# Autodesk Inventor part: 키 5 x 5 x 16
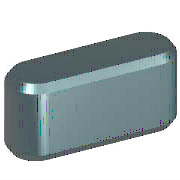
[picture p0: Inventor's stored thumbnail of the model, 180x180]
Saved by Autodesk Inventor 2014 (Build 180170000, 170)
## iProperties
IsCustomPart: 1
Created: 2012-02
Part Number: 키 5 x 5 x 16
Material: 강철, 연강
Description: 키 및 해당 키홈
Document SubType Name: Modeling
Standard: KS B 1311
Designer: mduedu
Standards Organization: KS
Language: ko-KR
Size Designation: 5 x 5 x 16
Categories: <MemberInstance><Categories><Category DisplayName="샤프트 부품" InternalName="7f7aeb1f-a693-4053-b835-cee3144e0d98" Mnemonic="SHFT"><Category DisplayName="키" Interna
Density: 1 g/cm^3
Appearance: 강철
Author: mduedu
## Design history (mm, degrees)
workplane "Work Plane1"
workplane "Work Plane2"
sketch "스케치1"
  geometry: L1 (2.5, 2.5)-(13.5, 2.5); L2 (13.5, -2.5)-(2.5, -2.5); L3 (0, 9.4)-(0, -7.4) reference; L4 (-5, 0)-(30, 0) reference; L5 (16, 0)-(16, 7); A1 r 2.5 centre (2.5, 0) between (2.5, 2.5) and (2.5, -2.5); A2 r 2.5 centre (13.5, 0) between (13.5, -2.5) and (13.5, 2.5)
  constraints: 6 end point, 5 point on circle, 4 tangent, 3 point on line, 2 centre point, 1 horizontal, 1 parallel, 1 perpendicular
  dimensions: "d0" = 2.5 radius of A1 (= 0.5 x PB); "d13" = 2.5 radius of A2 (= 0.5 x PB); "d14" = 16 distance between parallel lines of L5 L3 (= NLG)
extrude "본체1" new body sketch "스케치1" taper "d3" = 0 deg; stored distance "d4" = 10
workplane "Work Plane3"
body "Solid1"
chamfer "모따기1" distance "d8" = 0.4 (= PHH); stored, may be unused: second distance "d9" = 0.4 (= PHH), angle "d15" = 45 deg
other parameters: "d1" = -3 (= -PNT), "d2" = 2 (= PH - PNT), "NLG" = 16 [user parameter; used in 3 equation terms], "PB" = 5 [user parameter; used in 2 equation terms], "PNT" = 3 [user parameter; used in 2 equation terms], "PH" = 5 [user parameter; used in 1 equation term], "PHH" = 0.4 [user parameter; used in 2 equation terms], "d10" = 0, "d16" = 0, "d17" = 0, "d18" = 0, "WDMIN" = 12 [user parameter], "PLB2" = 16 (= NLG) [user parameter], "WDMAX" = 17 [user parameter], "PLB1" = 16 (= NLG) [user parameter], "RR" = 0.16 [user parameter], "PUEB" = 2.3 [user parameter]
